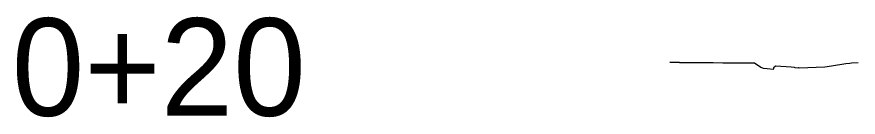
# Model space of a CAD drawing. Extents: x -577 to 1138, y -35 to 4556.
# Drawn here: x -468 to 135, y 1973 to 2045 of the extents above; entities that cross this region are included whole.
import ezdxf

# ---------------------------------------------------------------- set-up
doc = ezdxf.new("R2010")
doc.units = 0
doc.layers.add('SC_Scratch1', color=7, linetype='Continuous')
doc.layers.add('XS_X_Ground_Line', color=7, linetype='Continuous')

msp = doc.modelspace()

# ---------------------------------------------------------------- linework, layer by layer
at = {"layer": 'XS_X_Ground_Line'}
for p, q in [((0, 2012.46), (4.85, 2012.41)), ((4.85, 2012.41), (5.91, 2012.43)), ((5.91, 2012.43), (6.85, 2012.43)), ((6.85, 2012.43), (7.04, 2012.07)), ((7.04, 2012.07), (7.58, 2012.03)), ((7.58, 2012.03), (17.83, 2012.05)), ((17.83, 2012.05), (18.97, 2012.05)), ((18.97, 2012.05), (21.46, 2012.05)), ((21.46, 2012.05), (26.54, 2012.06)), ((26.54, 2012.06), (28.32, 2012.06)), ((28.32, 2012.06), (28.91, 2012.06)), ((28.91, 2012.06), (30.25, 2012.06)), ((30.25, 2012.06), (31.1, 2012.07)), ((31.1, 2012.07), (37.97, 2011.99)), ((37.97, 2011.99), (39.35, 2011.99)), ((39.35, 2011.99), (40.86, 2011.99)), ((40.86, 2011.99), (41.45, 2011.99)), ((41.45, 2011.99), (42.65, 2011.97)), ((42.65, 2011.97), (44.55, 2011.95)), ((44.55, 2011.95), (45.41, 2011.94)), ((45.41, 2011.94), (45.81, 2011.93)), ((45.81, 2011.93), (46.71, 2011.92)), ((46.71, 2011.92), (47.24, 2011.92)), ((47.24, 2011.92), (60.61, 2011.98)), ((60.61, 2011.98), (65.31, 2008.81)), ((65.31, 2008.81), (66.8, 2008.03)), ((74.26, 2007.45), (74.88, 2008.93)), ((74.88, 2008.93), (75.91, 2009.83)), ((75.91, 2009.83), (86.88, 2008.98)), ((86.88, 2008.98), (89.21, 2008.69)), ((89.21, 2008.69), (89.48, 2008.5)), ((89.48, 2008.5), (89.71, 2008.52)), ((89.71, 2008.52), (89.84, 2008.53)), ((89.84, 2008.53), (92.01, 2008.35)), ((92.01, 2008.35), (92.08, 2008.4)), ((92.08, 2008.4), (92.25, 2008.48)), ((92.25, 2008.48), (93.05, 2008.36)), ((93.05, 2008.36), (104.8, 2008.67)), ((104.8, 2008.67), (111.04, 2008.95)), ((111.04, 2008.95), (116, 2009.73)), ((116, 2009.73), (126.22, 2011.32)), ((126.22, 2011.32), (129.02, 2011.76)), ((129.02, 2011.76), (130.19, 2011.94)), ((130.19, 2011.94), (135, 2012.15)), ((66.8, 2008.03), (69.83, 2007.76)), ((69.83, 2007.76), (74.26, 2007.45))]:
    msp.add_line(p, q, dxfattribs=at)

# ---------------------------------------------------------------- texts
at = {"layer": 'SC_Scratch1'}
msp.add_text('0+20', height=70, dxfattribs=at).set_placement((-471.72, 1973.87))

doc.saveas('drawing.dxf')
